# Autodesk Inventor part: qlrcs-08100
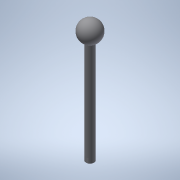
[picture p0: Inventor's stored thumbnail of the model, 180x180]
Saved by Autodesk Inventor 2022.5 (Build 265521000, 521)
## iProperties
Created: 2016-12
Part Number: qlrcs-08100
Material: 一般
Document SubType Name: Modeling
Designer: imaocorp
Density: 1 g/cm^3
Appearance: 既定
Author: imaocorp
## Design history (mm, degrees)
node "qlrcs-08100.x_t1"
node "qlrcs-08100"
node "Base1"
